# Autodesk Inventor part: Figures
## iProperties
Author: Renu Muthoo
Created: 2001-11
Part Number: Figures
Document SubType Name: Modeling
Designer: Renu Muthoo
Control State: 0
Master: False
Checked Out: False
PropertySet Name: Design Tracking Control
Shininess: 65.0
Angle Display Precision: 2
Document Length Units: 11269
Document Angle Units: 11283
Document Time Units: 11279
Document Mass Units: 11290
Document Length Units Precision: 3
Document Angle Units Precision: 2
Compacted: False
PropertySet Name: _Private Model Information
Density: 0.0
Volumn: 0.0
Area: 0.0
PropertySet Name: Model Information
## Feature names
1. Extrusion1
2. Extrusion2
3. Extrusion3
4. Hole1
